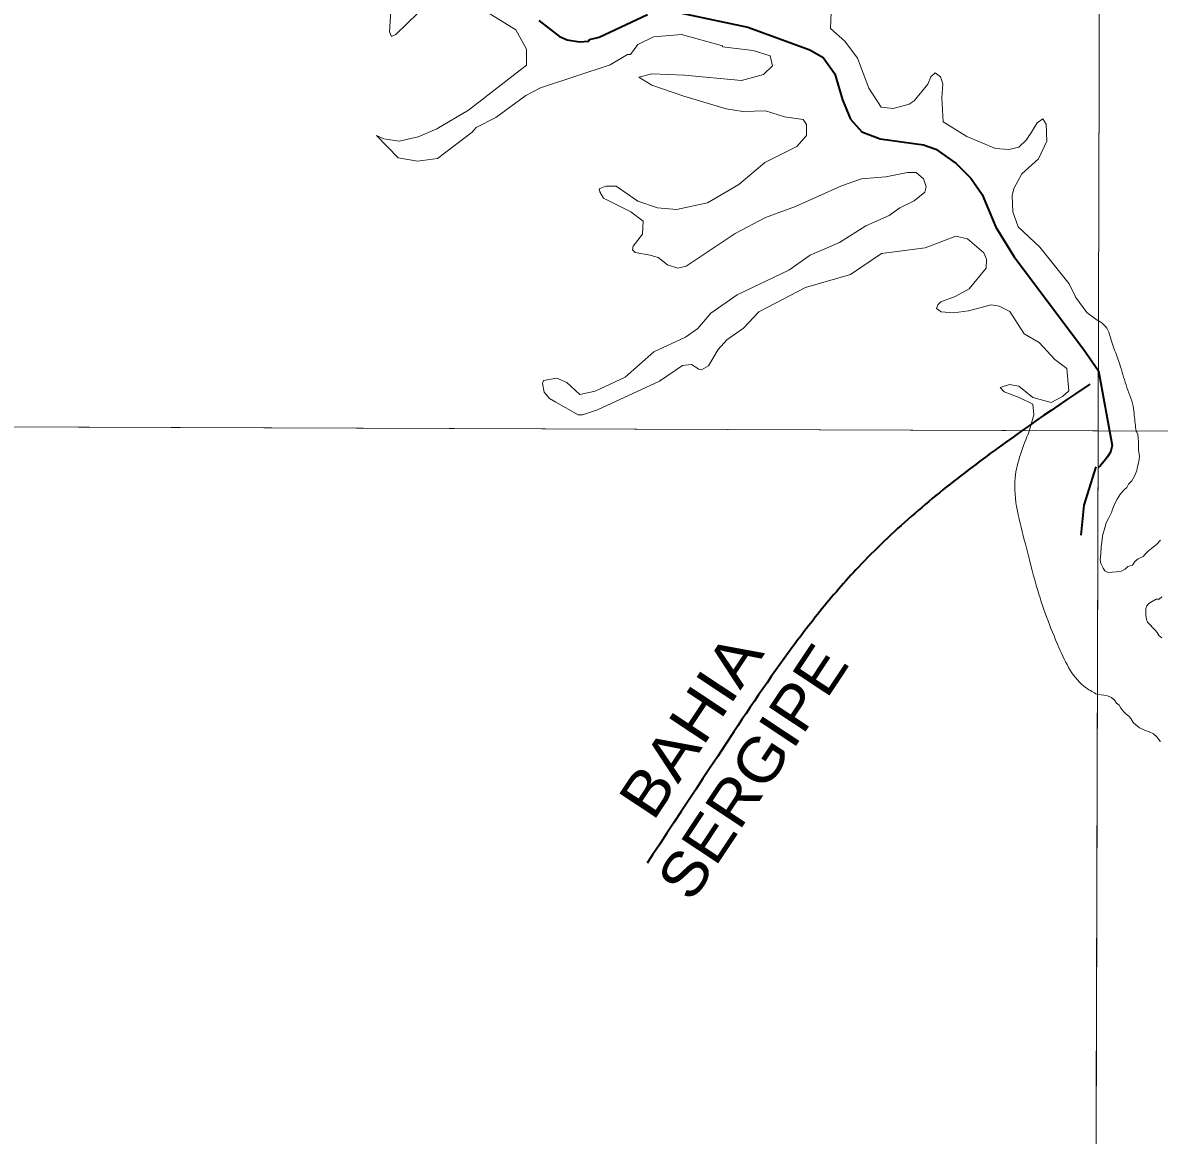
# Model space of a CAD drawing. Extents: x 553962 to 842807, y 8883888 to 9032388.
# Drawn here: x 583659 to 585726, y 8908688 to 8910712 of the extents above; entities that cross this region are included whole.
import ezdxf
from ezdxf.enums import TextEntityAlignment as Align

# ---------------------------------------------------------------- set-up
doc = ezdxf.new("R2010")
doc.units = 0
doc.header["$LTSCALE"] = 200
doc.linetypes.add('LONG_DASH_SHORT_DASH', pattern=[9.9, 6, -1.2, 1.5, -1.2])
doc.layers.add('6', color=7, linetype='Continuous', lineweight=13)

msp = doc.modelspace()

# ---------------------------------------------------------------- linework, layer by layer
at = {"layer": '6'}
msp.add_line((574653.9, 8910009.3), (626625.7, 8909822.1), dxfattribs=at)
for points in [[(585656.3, 8924738.8), (585614.8, 8909969.8), (585573.6, 8896026.7)], [(584328.8, 8910742.2), (584326.1, 8910695.4), (584329.5, 8910687), (584337.2, 8910690.8), (584398.2, 8910749.5)], [(584503.5, 8910731.6), (584555.8, 8910699.3), (584575.1, 8910664.3), (584575, 8910635.1)], [(585613, 8910170.9), (585594.1, 8910185.2), (585574.1, 8910212), (585562.3, 8910236.9), (585508.4, 8910303.8), (585469.5, 8910341.1), (585459.3, 8910368.4), (585458.6, 8910397.8), (585461.4, 8910410.8), (585476.2, 8910437.1), (585506.5, 8910464.7), (585521.5, 8910496.5), (585520.3, 8910527.4), (585514.3, 8910537.5), (585503.6, 8910530.2), (585491.9, 8910510), (585489.3, 8910507.2), (585484.3, 8910499.4), (585470.6, 8910485.7), (585452.1, 8910481.5), (585427.8, 8910483.5), (585376, 8910505.3), (585332.8, 8910531.9), (585330.2, 8910575.4), (585332.3, 8910601), (585328.2, 8910613.7), (585318.2, 8910620.8), (585310.2, 8910614), (585304.7, 8910600.1), (585280.3, 8910570.1), (585271.3, 8910563.7), (585242, 8910556.1), (585220.2, 8910558.3), (585197.6, 8910593.2), (585177.1, 8910647.8), (585154, 8910678.9), (585128, 8910701.8), (585129, 8910730.6)], [(584575, 8910635.1), (584469.8, 8910553.2), (584412.1, 8910519.2), (584378.1, 8910504.3), (584343.7, 8910496.8), (584315.6, 8910501), (584302.5, 8910506.7), (584341.7, 8910466.1), (584377, 8910460), (584413.4, 8910464.9), (584476.2, 8910513.3), (584483.2, 8910521.7), (584519.5, 8910539.6), (584574.1, 8910579.6), (584600.3, 8910593.5), (584727.1, 8910635.6), (584758.7, 8910654.2), (584764.1, 8910654.1), (584777.8, 8910672.8), (584805.8, 8910686.5), (584857.1, 8910690.5), (584931.6, 8910670.4), (584931.7, 8910668.3), (584987.4, 8910661.7), (585018.3, 8910652.2), (585022.5, 8910633.9), (585006, 8910617.9), (584965.8, 8910606.8), (584862.5, 8910616.7)], [(584862.5, 8910616.7), (584802.7, 8910619.4), (584779.5, 8910612.9), (584802.7, 8910598.3), (584861, 8910578.3), (584938.2, 8910555.3), (584968.8, 8910550.7), (585009.7, 8910552), (585044.2, 8910540.8), (585078.1, 8910536.3), (585084.6, 8910527), (585084.6, 8910506.7), (585066.6, 8910486.9), (585008.8, 8910457.8), (584961, 8910417.7), (584904.5, 8910384.2), (584847.7, 8910372.4), (584813.3, 8910375.5), (584777.6, 8910387.8), (584738.3, 8910414.6), (584719.6, 8910415), (584707.3, 8910410.1), (584708.3, 8910404.7), (584715.3, 8910392.9), (584764.8, 8910368.3), (584787.4, 8910351.4), (584785.9, 8910327.6), (584769.2, 8910305.8), (584767.6, 8910298.8), (584772.9, 8910294.4), (584800, 8910289.5), (584814.7, 8910285.1), (584831.6, 8910271.7), (584850.3, 8910265.6), (584865.5, 8910269.3), (584954.5, 8910328.5), (585009.6, 8910357.9), (585064.1, 8910377.6), (585147.9, 8910415.2), (585184.6, 8910428.3), (585228.5, 8910431.7), (585267.9, 8910439.7), (585283.9, 8910439.8), (585297.3, 8910428.1), (585301.8, 8910413.6), (585299.8, 8910404), (585279.9, 8910388.4), (585254.1, 8910375.6), (585234.4, 8910361.7), (585192.5, 8910342.6), (585144.1, 8910312.1), (585090.8, 8910289), (585052.1, 8910261.8), (584958.3, 8910216.9), (584910.5, 8910183.5), (584886.5, 8910155.6), (584864.3, 8910139.8), (584806.9, 8910113.4), (584754.7, 8910067.2), (584700, 8910041.6), (584672.2, 8910035.9), (584648.3, 8910057.9), (584630.4, 8910065.7), (584605.9, 8910061), (584603.9, 8910056.1)], [(584603.9, 8910056.1), (584607.2, 8910039.8), (584616.9, 8910028.5), (584628.5, 8910021.9), (584668.8, 8909998.9), (584676.7, 8909998.9), (584704, 8910007.6), (584817.2, 8910060.3), (584858.8, 8910088.5), (584875.1, 8910090.6), (584888.6, 8910081.7), (584893.5, 8910080.6), (584905.8, 8910088), (584923.7, 8910117.4), (584939.2, 8910135.5), (584969.7, 8910156.6), (584997.7, 8910186.3), (585082.5, 8910230.4), (585164.2, 8910254), (585220.6, 8910292.1), (585299.9, 8910302.5), (585355.9, 8910323.7), (585377.1, 8910318.9), (585407.1, 8910293.7), (585411.8, 8910281.8), (585411.3, 8910265.8), (585380.1, 8910228.3), (585354.8, 8910214.1), (585328.7, 8910204.3), (585323, 8910199), (585320.6, 8910192.2), (585329.2, 8910186.2), (585351.9, 8910184.5), (585378.8, 8910187.8), (585420.4, 8910199.1), (585435, 8910196.4)], [(585435, 8910196.4), (585454.1, 8910186.9), (585480.4, 8910146.2), (585507.6, 8910130.2), (585536, 8910099.4), (585557.7, 8910083.3), (585561.6, 8910042.2), (585550.1, 8910031.9), (585529.2, 8910021.5), (585495.8, 8910030.1), (585470.4, 8910050.8), (585453.4, 8910054.2), (585436.7, 8910048.7), (585443.6, 8910040.4), (585470.9, 8910030.2), (585495.8, 8910018), (585497.8, 8909999), (585489.3, 8909969)], [(585620.4, 8909758.5), (585621.7, 8909767), (585622.4, 8909778.7), (585626.9, 8909793), (585629.5, 8909802.2), (585634.1, 8909811.3), (585639.3, 8909821), (585640.6, 8909826.9), (585645.2, 8909837.3), (585649.1, 8909845.1), (585655.6, 8909854.9), (585662.1, 8909862.1), (585666.7, 8909866.6), (585669.9, 8909872.5), (585675.8, 8909879), (585681, 8909887.4), (585684.9, 8909897.8), (585686.2, 8909905), (585688.8, 8909914.1), (585690.1, 8909923.2), (585688, 8909935.1), (585688.1, 8909940.1), (585688.1, 8909944.1), (585688.2, 8909950.1), (585687.7, 8909956.1), (585686.8, 8909963.1), (585685.3, 8909967.1), (585683.7, 8909969.3)], [(585727.9, 8909770.9), (585721.4, 8909763.7), (585721.4, 8909763.7), (585711.6, 8909755.9), (585705.8, 8909750.7), (585705.8, 8909750.7), (585700.5, 8909745.5), (585696.6, 8909740.9), (585687.5, 8909737), (585682.3, 8909732.5), (585677.1, 8909725.3), (585668.6, 8909722.7), (585664.1, 8909718.2), (585656.9, 8909714.2), (585648.4, 8909712.9), (585640.3, 8909712.6), (585632.8, 8909711.7), (585632.8, 8909711.7), (585626.9, 8909714.9), (585623.7, 8909720.1), (585623.7, 8909720.1), (585619.8, 8909728.6), (585618.5, 8909735.1), (585619.8, 8909746.2), (585620.4, 8909758.5)], [(585730.3, 8909592.8), (585725.8, 8909596.9), (585721.9, 8909602.9), (585718.4, 8909606.9), (585714.9, 8909610.9), (585708.5, 8909617.5), (585704.5, 8909621.5), (585703, 8909626.6), (585701.6, 8909634.6), (585701.2, 8909642.1), (585701.2, 8909646.6), (585703.2, 8909651.1), (585706.8, 8909655.6), (585712.8, 8909659), (585720.3, 8909663.5), (585725.8, 8909663.4), (585730.4, 8909667.4)], [(585613.4, 8909490.1), (585625.1, 8909488.8), (585632, 8909487.3), (585638.9, 8909484.6), (585645, 8909479.2), (585648.1, 8909474.3), (585652.7, 8909470.4), (585655.8, 8909465.1), (585655.8, 8909465.1), (585661.5, 8909458.2), (585661.5, 8909458.2), (585665.7, 8909454.3), (585670.5, 8909450.3), (585674, 8909446.2), (585678.4, 8909439.2), (585683.4, 8909434.7), (585690.2, 8909429.4), (585690.2, 8909429.4), (585700.8, 8909424.5), (585707.3, 8909422), (585715.3, 8909418.4), (585721.7, 8909412.9), (585724.7, 8909408.8), (585728.2, 8909404.8)]]:
    msp.add_lwpolyline(points, dxfattribs=at)
for points in [[(585645.8, 8921027.3), (574684.9, 8921064.7), (574653.9, 8910009.3), (585614.8, 8909969.8)], [(596575.8, 8909932.4), (585614.8, 8909969.8), (585583.8, 8898914.4), (596544.8, 8898874.9)]]:
    msp.add_lwpolyline(points, close=True, dxfattribs=at)
at = {"layer": '6', "linetype": 'LONG_DASH_SHORT_DASH', "lineweight": 35}
for points in [[(584597.3, 8910716), (584635, 8910687.1), (584649.2, 8910681), (584671.7, 8910677.1), (584688.5, 8910678.4), (584689.9, 8910681.4), (584707.2, 8910685.8), (584795.4, 8910727.2)], [(584831.7, 8910735), (584977.8, 8910704.3), (585090.2, 8910662.8), (585114.4, 8910648.6), (585135.7, 8910619.1), (585149.9, 8910572.1), (585164.6, 8910536.6), (585184.9, 8910513.7), (585218.4, 8910500.7), (585296.9, 8910489.9), (585319.4, 8910482.1), (585356.6, 8910456.1), (585383.4, 8910429.4), (585403.7, 8910399.5), (585428.8, 8910340.2), (585462.1, 8910286.2), (585588.3, 8910118.5), (585615.1, 8910078.7)], [(585615.1, 8910078.7), (585640.3, 8909942.8), (585637.2, 8909930.8), (585631.7, 8909922.3), (585625.6, 8909914.8), (585619, 8909906.4), (585614.6, 8909902.8)], [(585583.7, 8909780.1), (585589.5, 8909834.4), (585611.1, 8909903.9)]]:
    msp.add_lwpolyline(points, dxfattribs=at)
at = {"layer": '6'}
for points in [[(585683.7, 8909969.3), (585680.5, 8909997.4), (585678.2, 8910014.6), (585665.5, 8910053.6), (585654.1, 8910090.4), (585639.2, 8910132.8), (585625.4, 8910162.7), (585613, 8910170.9)], [(585489.3, 8909969), (585463.9, 8909884.3), (585482.4, 8909764.2), (585502.7, 8909686.5), (585543.4, 8909575.6), (585593.3, 8909501.7), (585613.4, 8909490.1)]]:
    msp.add_spline(points, degree=3, dxfattribs=at)
at = {"layer": '6', "linetype": 'LONG_DASH_SHORT_DASH', "lineweight": 35}
msp.add_spline([(585599.5, 8910054.8), (585178.8, 8909721.7), (584922.2, 8909376.8), (584712.9, 8909059.8)], degree=3, dxfattribs=at)

# ---------------------------------------------------------------- texts
at = {"layer": '6'}
for s, width, p in [('BAHIA', 1.15, (584907.2, 8909411.3)), ('SERGIPE', 1.1, (585019.6, 8909327.4))]:
    msp.add_text(s, height=80, rotation=56.48, dxfattribs=dict(at, width=width)).set_placement(p, align=Align.CENTER)

doc.saveas('drawing.dxf')
